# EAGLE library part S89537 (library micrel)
Programmable Multi Output Bank Clock Synthesizer and Fanout Buffer, 3.3V Precision LVPECL and LVDS Source: http://www.micrel.com/_PDF/HBW/sy89537l.pdf
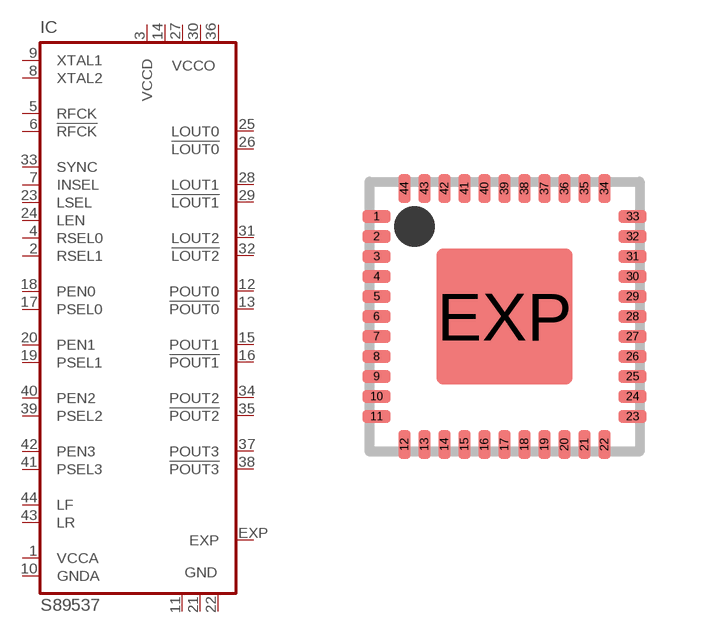
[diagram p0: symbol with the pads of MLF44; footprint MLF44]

Designator prefix IC

## S89537 (OC_FARNELL: unknown; OC_NEWARK: unknown)  [MLF44]
1  VCCA  pwr
2  RSEL1  in
3  VCCD  pwr
4  RSEL0  in
5  RFCK  in
6  !RFCK  in
7  INSEL  in
8  XTAL2  in
9  XTAL1  in
10  GNDA  pwr
11  GND  pwr
12  POUT0  out
13  !POUT0  out
14  VCCO  pwr
15  POUT1  out
16  !POUT1  out
17  PSEL0  in
18  PEN0  in
19  PSEL1  in
20  PEN1  in
21  GND  pwr
22  GND  pwr
23  LSEL  in
24  LEN  in
25  LOUT0  out
26  !LOUT0  out
27  VCCO  pwr
28  LOUT1  out
29  !LOUT1  out
30  VCCO  pwr
31  LOUT2  out
32  !LOUT2  out
33  SYNC  in
34  POUT2  out
35  !POUT2  out
36  VCCO  pwr
37  POUT3  out
38  !POUT3  out
39  PSEL2  in
40  PEN2  in
41  PSEL3  in
42  PEN3  in
43  LR
44  LF
EXP  EXP  pas

## Footprint MLF44 (pad centres in mm)
MLF-44 Micro Lead Frame Package Source: http://www.micrel.com/_PDF/HBW/sy89537l.pdf
smd 0.7 x 0.3: 1 -3.2,2.5; 2 -3.2,2; 3 -3.2,1.5; 4 -3.2,1; 5 -3.2,0.5; 6 -3.2,0; 7 -3.2,-0.5; 8 -3.2,-1; 9 -3.2,-1.5; 10 -3.2,-2; 11 -3.2,-2.5; 23 3.2,-2.5; 24 3.2,-2; 25 3.2,-1.5; 26 3.2,-1; 27 3.2,-0.5; 28 3.2,0; 29 3.2,0.5; 30 3.2,1; 31 3.2,1.5; 32 3.2,2; 33 3.2,2.5
smd 0.3 x 0.7: 12 -2.5,-3.2; 13 -2,-3.2; 14 -1.5,-3.2; 15 -1,-3.2; 16 -0.5,-3.2; 17 0,-3.2; 18 0.5,-3.2; 19 1,-3.2; 20 1.5,-3.2; 21 2,-3.2; 22 2.5,-3.2; 34 2.5,3.2; 35 2,3.2; 36 1.5,3.2; 37 1,3.2; 38 0.5,3.2; 39 0,3.2; 40 -0.5,3.2; 41 -1,3.2; 42 -1.5,3.2; 43 -2,3.2; 44 -2.5,3.2
smd 3.4 x 3.4: EXP 0,0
